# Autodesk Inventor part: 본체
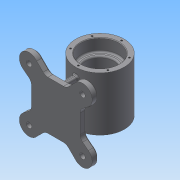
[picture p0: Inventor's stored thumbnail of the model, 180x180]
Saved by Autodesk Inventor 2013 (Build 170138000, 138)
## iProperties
Created: 2018-03
Part Number: 본체
Material: 일반
Document SubType Name: Modeling
Designer: Administrator
Density: 1 g/cm^3
Author: Administrator
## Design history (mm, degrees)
sketch "스케치2"
  geometry: C1 r 45 at (0, 0); 1 further point
  constraints: 1 centre point, 1 coincident
  dimensions: "d42" = 90 diameter of C1
extrude "돌출2" new body sketch "스케치2" stored distance "d44" = 100; taper "d45" = 0 deg
hole "구멍1" diameter "d48" = 70; stored, may be unused: countersink angle "d52" = 90 deg, drill point angle "d54" = 0 deg; dims "d46" = 10, "d47" = 10, "d49" = 6, "d50" = 4, "d51" = 2, "d53" = 23
hole "구멍2" diameter "d57" = 52; stored, may be unused: countersink angle "d61" = 90 deg, drill point angle "d63" = 0 deg; dims "d55" = 10, "d56" = 10, "d58" = 6, "d59" = 4, "d60" = 2, "d62" = 47
hole "구멍3" diameter "d66" = 40; stored, may be unused: countersink angle "d70" = 90 deg, drill point angle "d72" = 0 deg; dims "d64" = 10, "d65" = 10, "d67" = 6, "d68" = 4, "d69" = 2, "d71" = 30
node "작업 평면2"
sketch "스케치4"
  geometry: L1 (0, 0)-(-45, 0); L2 (-45, 0)-(-45, 45); L3 (-45, 45)-(0, 45); L4 (0, 45)-(0, 0); L5 (0, 0)-(-49.497, 49.497); L6 (0, 0)-(70, 0); L7 (-60.483, 35.239)-(-49.871, 27.062); L8 (-35.239, 60.483)-(-23.417, 48.661); L9 (0, 45)-(-14.578, 45); L10 (-45, 0)-(-45, 17.16); A1 r 70 centre (0, 0) between (-49.497, 49.497) and (-60.483, 35.239); A2 r 18 centre (-49.497, 49.497) between (-35.239, 60.483) and (-60.483, 35.239); A3 r 12.5 centre (-57.5, 17.16) between (-45, 17.16) and (-49.871, 27.062); A4 r 12.5 centre (-14.578, 57.5) between (-23.417, 48.661) and (-14.578, 45)
  constraints: 20 end point, 9 point on circle, 6 tangent, 4 centre point, 3 parallel, 2 coincident, 2 horizontal, 2 point on line, 1 collinear, 1 equal length, 1 perpendicular
  dimensions: "d74" = 45 distance of L2.end L3.end; "d75" = 45 distance of L1.end L2.end; "d76" = 140 diameter of A1; "d77" = 135 deg angle of L6 L5; "d78" = 36 diameter of A2; "d79" = 25 diameter of A3; "d80" = 25 diameter of A4
extrude "돌출3" join sketch "스케치4" distance "d81" = 12; taper "d82" = 0 deg
sketch "스케치5"
  geometry: L1 (-45, -82)-(-45, -70) reference; L2 (-45, -70)-(45, -70) reference; L3 (45, -70)-(45, -82) reference; L4 (45, -82)-(-45, -82) reference; L5 (21.342, -39.617)-(24, -70); L6 (-21.342, -39.617)-(-24, -70); L7 (-24, -70)-(0, -70); L8 (0, -70)-(24, -70); C1 r 26 at (0, 0) reference; A1 r 45 centre (0, 0) between (21.342, -39.617) and (-21.342, -39.617) reference; 1 further point
  constraints: 8 end point, 2 point on circle, 2 point on line, 1 collinear, 1 midpoint
  dimensions: "d85" = 24 distance of L6.end L7.end; "d86" = 24 distance of L5.end L7.end; "d87" = 95 deg angle of L5 L2; "d88" = 95 deg angle of L2 L6
  node "절단 모서리 투영1"
sketch "스케치6"
  geometry: L1 (35, 27)-(35, 50) reference; L2 (35, 50)-(45, 50) reference; L3 (45, 50)-(45, -50) reference; L4 (45, -50)-(20, -50) reference; L5 (20, -50)-(20, -20) reference; L6 (20, -20)-(26, -20) reference; L7 (26, -20)-(26, 27) reference; L8 (26, 27)-(35, 27) reference; L9 (-82, 45)-(-70, 45) reference; L10 (-70, 45)-(-70, -45) reference; L11 (-45, -50)-(-45, 50) reference; L12 (-45, 50)-(-35, 50) reference; L13 (-35, 50)-(-35, 27) reference; L14 (-35, 27)-(-26, 27) reference; L15 (-26, 27)-(-26, -20) reference; L16 (-26, -20)-(-20, -20) reference; L17 (-20, -20)-(-20, -50) reference; L18 (-20, -50)-(-45, -50) reference; L19 (-70, -45)-(-82, -45) reference; L20 (-82, -45)-(-82, 45) reference; L21 (-70, 4)-(-70, -4); L22 (-70, 0)-(-70, 37); L23 (-70, 37)-(-45, 37); L24 (-70, 0)-(-70, -37); L25 (-70, -37)-(-45, -37); 1 further point
  constraints: 10 end point, 4 point on line, 2 perpendicular, 1 midpoint, 1 parallel
  dimensions: "d93" = 37 distance of L22.start L22.end; "d156" = 37 distance of L22.start L24.end
  node "절단 모서리 투영2"
sketch "스케치7"
  geometry: A1 r 45 centre (0, 0) between (45, 0) and (45, 0) reference; 1 further point
  constraints: 1 vertical alignment
  dimensions: "d97" = 40 distance of A1.centre point (0, 40)
hole "구멍4" sketch "스케치7" at (0, 40) diameter "d98" = 3.242; stored, may be unused: countersink angle "d102" = 90 deg, drill point angle "d104" = 118 deg; dims "d99" = 9, "d100" = 4, "d101" = 2, "d103" = 11
node "작업 평면3"
sketch "스케치8"
  geometry: L1 (-12.5, -12.5)-(12.5, -12.5); L2 (12.5, -12.5)-(12.5, 12.5); L3 (12.5, 12.5)-(-12.5, 12.5); L4 (-12.5, 12.5)-(-12.5, -12.5); L5 (-12.5, -12.5)-(12.5, 12.5); L6 (12.5, -12.5)-(-12.5, 12.5); 1 further point
  constraints: 12 end point, 2 midpoint, 2 parallel, 1 horizontal, 1 perpendicular
  dimensions: "d108" = 25 distance of L3.end L2.end; "d109" = 25 distance of L2.end L1.end
extrude "돌출6" join sketch "스케치8" stored distance "d110" = 8; taper "d111" = 0 deg
sketch "스케치9"
  geometry: L1 (-7.5, -7.5)-(7.5, -7.5); L2 (7.5, -7.5)-(7.5, 7.5); L3 (7.5, 7.5)-(-7.5, 7.5); L4 (-7.5, 7.5)-(-7.5, -7.5); L5 (-7.5, -7.5)-(7.5, 7.5); L6 (7.5, -7.5)-(-7.5, 7.5); 1 further point
  constraints: 12 end point, 2 midpoint, 2 parallel, 1 horizontal, 1 perpendicular
  dimensions: "d112" = 15 distance of L3.end L2.end; "d113" = 15 distance of L2.end L1.end
extrude "돌출7" cut sketch "스케치9" stored distance "d114" = 8; taper "d115" = 0 deg
sketch "스케치10"
  geometry: C1 r 5 at (49.497, 49.497); C2 r 5 at (-49.497, 49.497); C3 r 5 at (-49.497, -49.497); C4 r 5 at (49.497, -49.497); A1 r 18 centre (49.497, 49.497) between (60.483, 35.239) and (35.239, 60.483) reference; A2 r 18 centre (49.497, -49.497) between (35.239, -60.483) and (60.483, -35.239) reference; A3 r 18 centre (-49.497, 49.497) between (-35.239, 60.483) and (-60.483, 35.239) reference; A4 r 18 centre (-49.497, -49.497) between (-60.483, -35.239) and (-35.239, -60.483) reference; 1 further point
  constraints: 4 centre point, 4 coincident
  dimensions: "d116" = 10 diameter of C1; "d122" = 5 radius of C2; "d123" = 5 radius of C3; "d124" = 5 radius of C4
extrude "돌출8" cut sketch "스케치10" stored distance "d119" = 8; taper "d120" = 0 deg
chamfer "모따기1" distance "d125" = 3; stored, may be unused: second distance "d126" = 2, angle "d127" = 45 deg
feature "리브1" dims "d128" = 1, "d129" = 8, "d130" = 0, "d131" = 0, "d132" = 1, "d133" = 1
feature "리브2" dims "d134" = 1, "d135" = 8, "d136" = 0, "d137" = 0, "d138" = 1, "d139" = 1
fillet "모깎기1" dims "d140" = 3
fillet "모깎기2" dims "d141" = 3
fillet "모깎기3" dims "d142" = 3
chamfer "모따기2" distance "d143" = 1; stored, may be unused: second distance "d144" = 2, angle "d145" = 45 deg
fillet "모깎기4" dims "d146" = 3
fillet "모깎기5" dims "d147" = 3
fillet "모깎기6" dims "d148" = 3
chamfer "모따기3" distance "d149" = 1; stored, may be unused: second distance "d150" = 2, angle "d151" = 45 deg
fillet "모깎기7" dims "d152" = 8
sketch "스케치11"
  geometry: 2 further points
  constraints: 1 horizontal alignment, 1 other
  dimensions: "d153" = 35 distance of point (35, 0) point (0, 0)
feature "엠보싱1" sketch "스케치11" dims "d154" = 0.5, "d155" = 0
node "솔리드2"
mirror "대칭3"
mirror "대칭4"
pattern_circular "원형 패턴1" dims angle "d106" = 360 deg
other parameters: "d73" = -82
